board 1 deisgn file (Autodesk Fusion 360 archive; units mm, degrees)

design "A2Z"
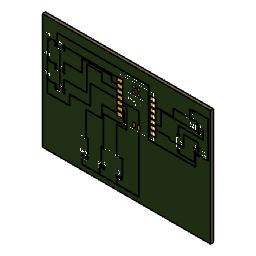
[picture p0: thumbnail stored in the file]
sketch "Outline" plane through (0, 0, 0) normal (0, 0, 1) x axis (1, 0, 0)
  line L1 (114.3, 44.45) -> (27.94, 44.45)
  line L2 (114.3, 103.81) -> (114.3, 44.45)
  line L3 (27.94, 103.81) -> (114.3, 103.81)
  line L4 (27.94, 44.45) -> (27.94, 103.81)
canvas "Canvas1"
canvas "Canvas2"
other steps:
base_feature "Base Feature1"
extrude "Extrude1" sketch "Outline" blind 1.5 bodies "Board"
pcbextrude "PCBExtrude1"
pcbextrude "PCBExtrude1"
pcbextrude "PCBExtrude1"
pcbextrude "PCBExtrude1"
base_feature "Base Feature1"
base_feature "Base Feature1"
box_primitive "BoxPrimitive1" DistanceX 20 DistanceY 18.89 DistanceZ 1 OffsetDistanceX 0 OffsetDistanceY 0
box_primitive "BoxPrimitive1" DistanceX 5 DistanceY 2.6 DistanceZ 0.99 OffsetDistanceX 0 OffsetDistanceY 0
base_feature "Base Feature1"
base_feature "Base Feature1"
pcbextrude "PCBExtrude1"
pcbhole "PCBHole1"
pcbhole "PCBHole1"
pcbextrude "PCBExtrude2" bodies "CopperHoles"
pcbhole "PCBHole2"
pcbhole "PCBHole2"
pcbhole "PCBHole1"
pcbhole "PCBHole2"
create_component "CreateComponent1"
create_component "CreateComponent2"
create_component "CreateComponent3"
create_component "CreateComponent4"
create_component "CreateComponent5"
create_component "CreateComponent6"
create_component "CreateComponent1"
create_component "CreateComponent2"
create_component "CreateComponent3"
create_component "CreateComponent4"
create_component "CreateComponent5"
create_component "CreateComponent1"
create_component "CreateComponent6"
as_built_joint "As-built1"
named bodies: "Board", "CopperHoles"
